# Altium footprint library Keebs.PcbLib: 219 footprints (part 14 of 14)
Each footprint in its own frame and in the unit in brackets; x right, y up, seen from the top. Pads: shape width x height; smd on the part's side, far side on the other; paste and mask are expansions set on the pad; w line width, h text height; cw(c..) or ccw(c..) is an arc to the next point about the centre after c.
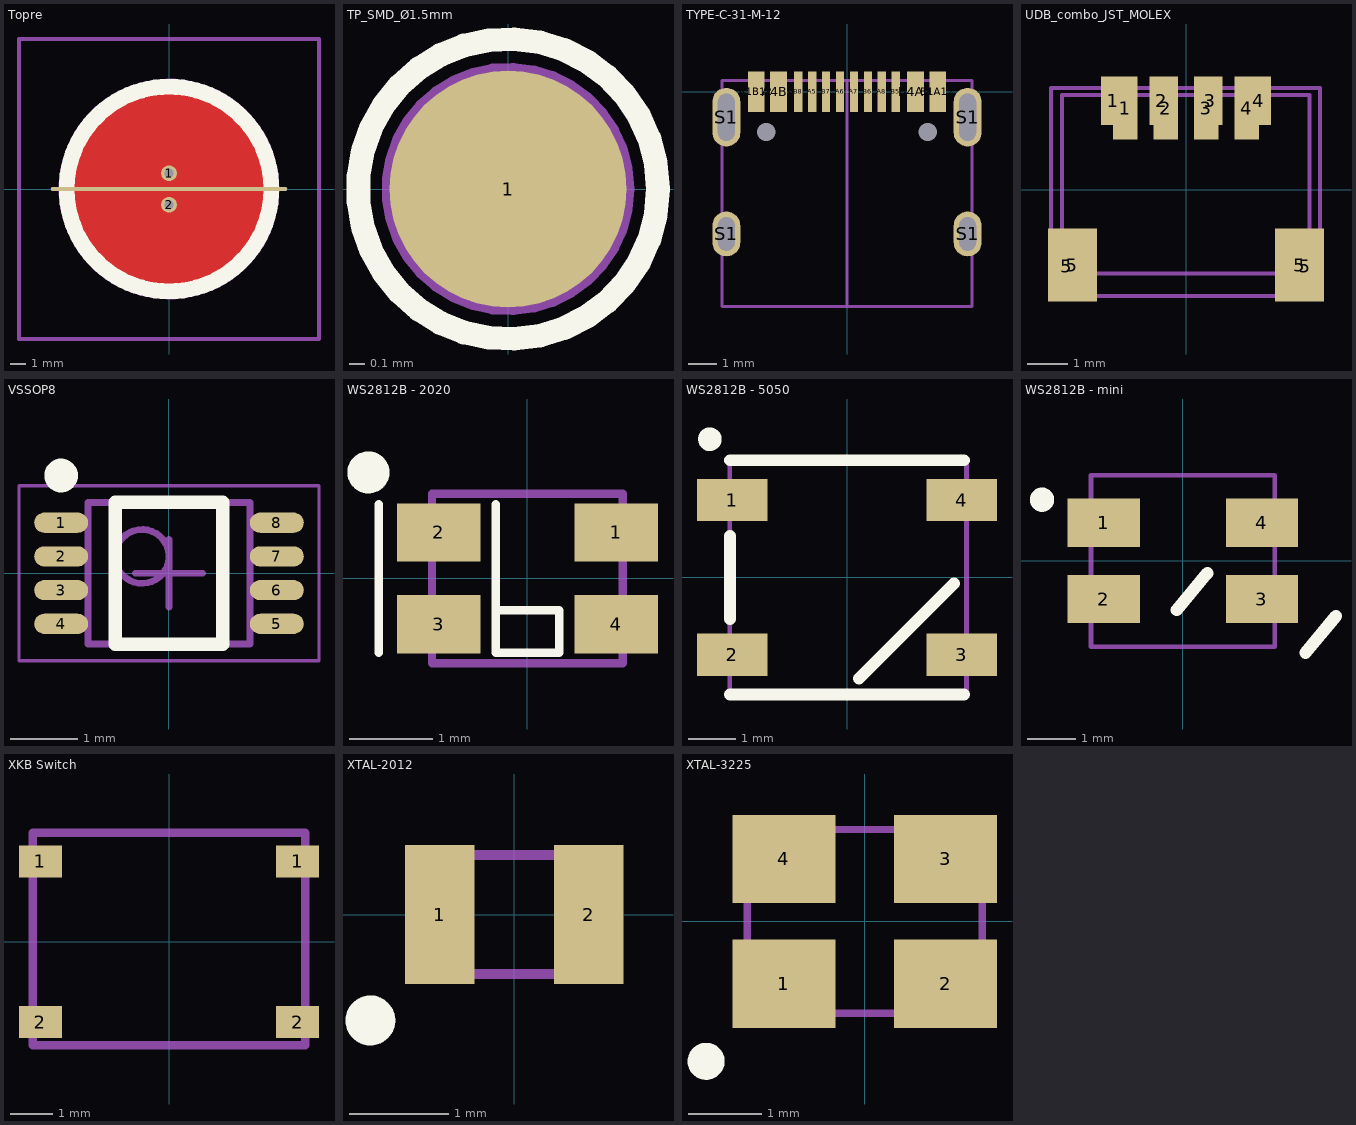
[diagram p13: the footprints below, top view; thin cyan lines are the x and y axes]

## Topre [mm]
pads (5):
  round 1 hole 0.6 mask+0: 1(0,1) 2(0,-1)
  oval 15x0.25 smd paste-1 mask+0: 3(0,0)
  oval 15x0.25 smd far side paste-1 mask+0: 3(0,0)
  round 1 on Mech13: ""(0,0)
Top Layer:
  pour cut-out: 0,-6.884 -0.338,-6.884 -1.011,-6.818 -1.675,-6.686 -2.322,-6.489 -2.947,-6.23 -3.543,-5.912 -4.106,-5.536 -4.628,-5.107 -5.107,-4.628 -5.536,-4.106 -5.912,-3.543 -6.23,-2.947 -6.489,-2.322 -6.686,-1.675 -6.818,-1.011 -6.884,-0.338 -6.884,0 -6.884,0.338 -6.818,1.011 -6.686,1.675 -6.489,2.322 -6.23,2.947 -5.912,3.543 -5.536,4.106 -5.107,4.628 -4.628,5.107 -4.106,5.536 -3.543,5.912 -2.947,6.23 -2.322,6.489 -1.675,6.686 -1.011,6.818 -0.338,6.884 0,6.884 0.338,6.884 1.011,6.818 1.675,6.686 2.322,6.489 2.947,6.23 3.543,5.912 4.106,5.536 4.628,5.107 5.107,4.628 5.536,4.106 5.912,3.543 6.23,2.947 6.489,2.322 6.686,1.675 6.818,1.011 6.884,0.338 6.884,0 6.884,-0.338 6.818,-1.011 6.686,-1.675 6.489,-2.322 6.23,-2.947 5.912,-3.543 5.536,-4.106 5.107,-4.628 4.628,-5.107 4.106,-5.536 3.543,-5.912 2.947,-6.23 2.322,-6.489 1.675,-6.686 1.011,-6.818 0.338,-6.884
  region: -5.259,0.414 -5.237,0.409 -5.193,0.401 -5.148,0.395 -5.103,0.393 -5.08,0.393 5.08,0.393 5.103,0.393 5.148,0.395 5.193,0.401 5.237,0.409 5.259,0.414 5.386,0.44 5.608,0.575 5.772,0.775 5.859,1.02 5.859,1.149 5.859,1.17 5.857,1.212 5.852,1.253 5.845,1.294 5.841,1.314 5.767,1.643 5.546,2.28 5.255,2.888 4.898,3.459 4.479,3.987 4.003,4.464 3.477,4.885 2.907,5.245 2.3,5.538 1.664,5.761 1.007,5.911 0.337,5.987 -0.337,5.987 -1.007,5.911 -1.664,5.761 -2.3,5.538 -2.907,5.245 -3.477,4.885 -4.003,4.464 -4.479,3.987 -4.898,3.459 -5.255,2.888 -5.546,2.28 -5.767,1.643 -5.841,1.314 -5.857,1.241 -5.861,1.092 -5.834,0.944 -5.779,0.805 -5.698,0.679 -5.594,0.572 -5.47,0.488 -5.332,0.429
  region: -5.841,-1.314 -5.767,-1.643 -5.546,-2.28 -5.255,-2.888 -4.898,-3.459 -4.479,-3.987 -4.003,-4.464 -3.477,-4.885 -2.907,-5.245 -2.3,-5.538 -1.664,-5.761 -1.007,-5.911 -0.337,-5.987 0.337,-5.987 1.007,-5.911 1.664,-5.761 2.3,-5.538 2.907,-5.245 3.477,-4.885 4.003,-4.464 4.479,-3.987 4.898,-3.459 5.255,-2.888 5.546,-2.28 5.767,-1.643 5.841,-1.314 5.845,-1.294 5.852,-1.253 5.857,-1.212 5.859,-1.17 5.859,-1.149 5.859,-1.02 5.772,-0.775 5.608,-0.575 5.386,-0.44 5.259,-0.414 5.237,-0.409 5.193,-0.401 5.148,-0.395 5.103,-0.393 5.08,-0.393 -5.08,-0.393 -5.103,-0.393 -5.148,-0.395 -5.193,-0.401 -5.237,-0.409 -5.259,-0.414 -5.332,-0.429 -5.47,-0.488 -5.594,-0.572 -5.698,-0.679 -5.779,-0.805 -5.834,-0.944 -5.861,-1.092 -5.857,-1.241
Bottom Layer:
  pour cut-out: 0,-6.884 -0.338,-6.884 -1.011,-6.818 -1.675,-6.686 -2.322,-6.489 -2.947,-6.23 -3.543,-5.912 -4.106,-5.536 -4.628,-5.107 -5.107,-4.628 -5.536,-4.106 -5.912,-3.543 -6.23,-2.947 -6.489,-2.322 -6.686,-1.675 -6.818,-1.011 -6.884,-0.338 -6.884,0 -6.884,0.338 -6.818,1.011 -6.686,1.675 -6.489,2.322 -6.23,2.947 -5.912,3.543 -5.536,4.106 -5.107,4.628 -4.628,5.107 -4.106,5.536 -3.543,5.912 -2.947,6.23 -2.322,6.489 -1.675,6.686 -1.011,6.818 -0.338,6.884 0,6.884 0.338,6.884 1.011,6.818 1.675,6.686 2.322,6.489 2.947,6.23 3.543,5.912 4.106,5.536 4.628,5.107 5.107,4.628 5.536,4.106 5.912,3.543 6.23,2.947 6.489,2.322 6.686,1.675 6.818,1.011 6.884,0.338 6.884,0 6.884,-0.338 6.818,-1.011 6.686,-1.675 6.489,-2.322 6.23,-2.947 5.912,-3.543 5.536,-4.106 5.107,-4.628 4.628,-5.107 4.106,-5.536 3.543,-5.912 2.947,-6.23 2.322,-6.489 1.675,-6.686 1.011,-6.818 0.338,-6.884
  pour cut-out: -6.51,0 -6.51,-0.319 -6.447,-0.955 -6.323,-1.581 -6.137,-2.192 -5.893,-2.782 -5.592,-3.346 -5.237,-3.877 -4.832,-4.37 -4.38,-4.822 -3.887,-5.227 -3.356,-5.582 -2.792,-5.883 -2.202,-6.127 -1.591,-6.313 -0.965,-6.437 -0.329,-6.5 -0.01,-6.5 0.309,-6.5 0.945,-6.437 1.571,-6.313 2.182,-6.127 2.772,-5.883 3.336,-5.582 3.867,-5.227 4.36,-4.822 4.812,-4.37 5.217,-3.877 5.572,-3.346 5.873,-2.782 6.117,-2.192 6.303,-1.581 6.427,-0.955 6.49,-0.319 6.49,0 6.49,0.319 6.427,0.955 6.303,1.581 6.117,2.192 5.873,2.782 5.572,3.346 5.217,3.877 4.812,4.37 4.36,4.822 3.867,5.227 3.336,5.582 2.772,5.883 2.182,6.127 1.571,6.313 0.945,6.437 0.309,6.5 -0.01,6.5 -0.329,6.5 -0.965,6.437 -1.591,6.313 -2.202,6.127 -2.792,5.883 -3.356,5.582 -3.887,5.227 -4.38,4.822 -4.832,4.37 -5.237,3.877 -5.592,3.346 -5.893,2.782 -6.137,2.192 -6.323,1.581 -6.447,0.955 -6.51,0.319
Top Overlay:
  circle w1: c0,0 r6.5
Mechanical 13:
  circle w0.254: c0,0 r6.884
  lines w0.254: -9.525,-9.525 9.525,-9.525 9.525,9.525 -9.525,9.525 -9.525,-9.525
  text ".Designator" at -7.366,-8.382 h1.5

## TP_SMD_Ø1.5mm [mm]
pads (1):
  round 1.5 smd paste-5: 1(0,0)
Top Overlay:
  circle w0.15: c0,0 r0.95
Mechanical 7:
  circle w0.1: c0,0 r0.95
  circle w0.1: c0,0 r0.75
  text ".Designator" at -0.9,1.175 h0.38

## TYPE-C-31-M-12 [mm]
pads (18):
  rect 0.6x1.45 smd: A1B12(-3.25,0) A4B9(-2.45,0) B1A12(3.25,0) B4A9(2.45,0)
  rect 0.3x1.45 smd: A5(-1.25,0) A6(-0.25,0) A7(0.25,0) A8(1.25,0) B5(1.75,0) B6(0.75,0) B7(-0.75,0) B8(-1.75,0)
  oval 1x1.6 / inner oval 1x1.6 / far side oval 1.3x2 hole 0.6 slot 1.2 at 90 deg: S1(-4.32,-5.095) S1(4.32,-5.095)
  oval 1x2.1 / inner oval 1x2.1 / far side oval 1.3x2.4 hole 0.6 slot 1.7 at 90 deg: S1(-4.32,-0.915) S1(4.32,-0.915)
  round 0 hole 0.65 unplated: ""(-2.89,-1.445) ""(2.89,-1.445)
Mechanical 13:
  lines w0.1: -4.47,-7.695 4.47,-7.695 4.47,0.395 -4.47,0.395 -4.47,-7.695
  text ".Designator" at -3.725,-3.7 h0.7
Mechanical 15:
  lines w0.1: 0,-7.695 0,0.395
  text "connector edge" at -2.95,-7.25 h1
3D body "HRO  TYPE-C-31-M-12.step": height 3.21, standoff -1, extent -4.475,-7.725 4.465,0.175

## UDB_combo_JST_MOLEX [mm]
pads (12):
  rect 0.6x1.2 smd: 1(-1.8,2.2) 2(-0.6,2.2) 3(0.6,2.2) 4(1.8,2.2)
  rect 0.6x1.55 smd: 1(-1.5,2.021) 2(-0.5,2.021) 3(0.5,2.021) 4(1.5,2.021)
  rect 0.85x1 smd: 5(-2.94,-1.887) 5(2.94,-1.887)
  rect 1.2x1.8 smd: 5(-2.8,-1.854) 5(2.8,-1.854)
Mechanical 13:
  lines w0.1: -3.327,-2.057 3.302,-2.057 3.302,2.515 -3.327,2.515 -3.327,-2.057 ; -3.054,-2.616 3.042,-2.616 3.042,2.337 -3.054,2.337 -3.054,-2.616
  text ".Designator" at -2.591,-0.178 h0.7
3D body "SM04B-SRSS-TB.STEP": height 2.96, standoff 0, extent -3.006,-2.616 2.994,2.334

## VSSOP8 [mm] "Dimensions from SN74LVC2G08DCUR"
height 0.9
pads (8):
  oval 0.8x0.3 smd: 1(-1.6,0.75) 2(-1.6,0.25) 3(-1.6,-0.25) 4(-1.6,-0.75) 5(1.6,-0.75) 6(1.6,-0.25) 7(1.6,0.25) 8(1.6,0.75)
Top Overlay:
  circle w0.25: c-1.6,1.45 r0.125
  lines w0.2: -0.8,-1.05 -0.8,1.05 0.8,1.05 0.8,-1.05 -0.8,-1.05
Mechanical 13:
  circle w0.1: c-0.4,0.25 r0.4
  lines w0.1: -1.2,-1.05 -1.2,1.05 1.2,1.05 1.2,-1.05 -1.2,-1.05
  text ".Designator" at -1.143,-0.762 h0.35
Mechanical 15:
  lines w0.05: -2.225,-1.3 -2.225,1.3 2.225,1.3 2.225,-1.3 -2.225,-1.3
  lines w0.1: -0.5,0 0.5,0 ; 0,-0.5 0,0.5
3D body "VSSOP8.step": height 0.9, standoff 0, extent -1.549,-1.05 1.549,1.05

## WS2812B - 2020 [mm]
pads (4):
  rect 1x0.7 smd: 1(1.065,0.55) 2(-1.065,0.55) 3(-1.065,-0.55) 4(1.065,-0.55)
Top Overlay:
  circle w0.254: c-1.905,1.27 r0.125
  lines w0.1: -1.782,-0.891 -1.782,0.887 ; -0.381,0.889 -0.381,-0.889 ; -0.381,-0.889 0.381,-0.889 0.381,-0.381 -0.381,-0.381 -0.381,-0.889
Mechanical 13:
  lines w0.1: -1.143,-1.016 -1.143,1.016 1.143,1.016 1.143,-1.016 -1.143,-1.016
  text ".Designator" at 1.016,0.127 h0.3
3D body "WS2812-2020.STEP": height 0.86, standoff 0, extent -1.1,-1 1.1,1

## WS2812B - 5050 [mm]
pads (4):
  rect 1.5x0.9 smd: 1(-2.45,1.65) 2(-2.45,-1.65) 3(2.45,-1.65) 4(2.45,1.65)
Top Overlay:
  circle w0.254: c-2.925,2.95 r0.125
  lines w0.254: -2.5,-2.5 2.5,-2.5 ; -2.5,-0.889 -2.5,0.889 ; -2.5,2.5 2.5,2.5 ; 0.254,-2.159 2.286,-0.127
Mechanical 13:
  lines w0.1: 2.5,-2.5 -2.5,-2.5 -2.5,2.5 2.5,2.5 ; 2.55,-2.5 2.55,2.5
  text ".Designator" at -2.275,-0.425 h0.6
3D body "WS2812_RGB_LED_updated.stp": height 1.5, standoff -0.2, extent -2.65,-2.45 2.7,2.5

## WS2812B - mini [mm]
pads (4):
  rect 1.5x1 smd: 1(-1.64,0.79) 2(-1.64,-0.79) 3(1.64,-0.79) 4(1.64,0.79)
Top Overlay:
  circle w0.254: c-2.921,1.27 r0.125
  lines w0.254: -0.127,-1.016 0.508,-0.254 ; 2.54,-1.905 3.175,-1.143
Mechanical 13:
  lines w0.1: -1.905,-1.778 1.905,-1.778 1.905,1.778 -1.905,1.778 -1.905,-1.778
  text ".Designator" at -1.651,0.127 h0.6
3D body "SMD WS2812B Mini.step": height 2, standoff 0.05, extent -1.84,-1.74 1.84,1.74

## XKB Switch [mm] "XKB Enterprise TS-1187A-C-D-B"
pads (4):
  rect 1x0.75 smd: 1(-3,1.875) 1(3,1.875) 2(-3,-1.875) 2(3,-1.875)
Mechanical 13:
  lines w0.2: -3.175,-2.413 3.175,-2.413 3.175,2.54 -3.175,2.54 -3.175,-2.413
  text ".Designator" at -1.397,0.762 h0.35
3D body "ts-1187a-a-d-b.stp": height 2, standoff 0, extent -3.25,-2.55 3.25,2.55

## XTAL-2012 [mm]
pads (2):
  rect 0.7x1.4 smd: 1(-0.75,0) 2(0.75,0)
Top Overlay:
  circle w0.254: c-1.448,-1.067 r0.125
Mechanical 13:
  lines w0.1: -1.025,-0.6 -1.025,0.6 1.025,0.6 1.025,-0.6 -1.025,-0.6
  text ".Designator" at -0.813,-0.127 h0.35

## XTAL-3225 [mm]
pads (4):
  rect 1.4x1.2 smd: 1(-1.1,-0.85) 2(1.1,-0.85) 3(1.1,0.85) 4(-1.1,0.85)
Top Overlay:
  circle w0.254: c-2.159,-1.905 r0.125
Mechanical 13:
  lines w0.1: -1.6,-1.25 1.6,-1.25 1.6,1.25 -1.6,1.25 -1.6,-1.25
  text ".Designator" at -1.397,-0.127 h0.35
3D body "3225 SMD Crystal Oscillator.STEP": height 0.65, standoff -0.05, extent -1.6,-1.25 1.6,1.25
